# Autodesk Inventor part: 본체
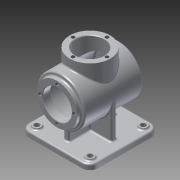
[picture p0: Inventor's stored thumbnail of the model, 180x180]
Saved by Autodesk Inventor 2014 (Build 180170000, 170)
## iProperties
Created: 2015-07
Part Number: 본체
Material: 알루미늄 6061
Document SubType Name: Modeling
Designer: L10
Density: 2.71 g/cm^3
Appearance: 알루미늄 - 평지
Author: L10
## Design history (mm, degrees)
sketch "스케치1"
  geometry: L1 (50, -65)-(-50, -65); L2 (-65, -50)-(-65, 50); L3 (-50, 65)-(50, 65); L4 (65, 50)-(65, -50); L5 (65, -65)-(-65, 65); L6 (-65, -65)-(65, 65); A1 r 15 centre (-50, 50) between (-50, 65) and (-65, 50); A2 r 15 centre (50, 50) between (65, 50) and (50, 65); A3 r 15 centre (50, -50) between (50, -65) and (65, -50); A4 r 15 centre (-50, -50) between (-65, -50) and (-50, -65); 1 further point
  constraints: 12 end point, 8 point on circle, 8 point on line, 8 tangent, 4 centre point, 3 equal radius, 2 midpoint, 2 parallel, 1 horizontal, 1 perpendicular
  dimensions: "d0" = 130 distance of L5.end L6.end; "d1" = 130 distance of L6.start L5.end; "d2" = 15 radius of A1
extrude "돌출1" new body sketch "스케치1" distance "d3" = 10; taper "d4" = 0 deg
fillet "모깎기1" dims "d5" = 3
sketch "스케치2"
  geometry: C1 r 7.5 at (-50, 50); C2 r 7.5 at (50, 50); C3 r 7.5 at (50, -50); C4 r 7.5 at (-50, -50); A1 r 12 centre (50, 50) between (62, 50) and (50, 62) reference; A2 r 12 centre (-50, 50) between (-50, 62) and (-62, 50) reference; A3 r 12 centre (-50, -50) between (-62, -50) and (-50, -62) reference; A4 r 12 centre (50, -50) between (50, -62) and (62, -50) reference; 1 further point
  constraints: 4 centre point, 4 coincident
  dimensions: "d6" = 15 diameter of C1; "d7" = 15 diameter of C2
extrude "돌출2" join sketch "스케치2" distance "d8" = 3; taper "d9" = 0 deg
fillet "모깎기2" dims "d10" = 3
hole "구멍1" diameter "d13" = 10; stored, may be unused: countersink angle "d17" = 90 deg, drill point angle "d19" = 118 deg; dims "d11" = 10, "d12" = 10, "d14" = 6, "d15" = 4, "d16" = 2, "d18" = 8
hole "구멍2" diameter "d22" = 10; stored, may be unused: countersink angle "d26" = 90 deg, drill point angle "d28" = 118 deg; dims "d20" = 10, "d21" = 10, "d23" = 6, "d24" = 4, "d25" = 2, "d27" = 8
hole "구멍3" diameter "d31" = 10; stored, may be unused: countersink angle "d35" = 90 deg, drill point angle "d37" = 118 deg; dims "d29" = 10, "d30" = 10, "d32" = 6, "d33" = 4, "d34" = 2, "d36" = 8
hole "구멍4" diameter "d40" = 10; stored, may be unused: countersink angle "d44" = 90 deg, drill point angle "d46" = 118 deg; dims "d38" = 10, "d39" = 10, "d41" = 6, "d42" = 4, "d43" = 2, "d45" = 8
sketch "스케치3"
  geometry: L1 (-45, -5)-(45, -5); L2 (45, -5)-(45, 5); L3 (45, 5)-(-45, 5); L4 (-45, 5)-(-45, -5); L5 (-45, -5)-(45, 5); L6 (45, -5)-(-45, 5); L7 (-5, -45)-(5, -45); L8 (5, -45)-(5, 45); L9 (5, 45)-(-5, 45); L10 (-5, 45)-(-5, -45); L11 (-5, -45)-(5, 45); L12 (5, -45)-(-5, 45); 1 further point
  constraints: 24 end point, 4 midpoint, 4 parallel, 2 horizontal, 2 perpendicular
  dimensions: "d47" = 90 distance of L3.end L2.end; "d48" = 10 distance of L2.end L1.end; "d49" = 10 distance of L9.end L8.end; "d50" = 90 distance of L8.end L7.end
extrude "돌출3" join sketch "스케치3" distance "d51" = 68; taper "d52" = 0 deg
fillet "모깎기3" dims "d53" = 3
sketch "스케치4"
  geometry: C1 r 38 at (0, 0); 1 further point
  constraints: 1 centre point, 1 coincident
  dimensions: "d54" = 76 diameter of C1
extrude "돌출4" join sketch "스케치4" distance "d55" = 62; taper "d56" = 0 deg
sketch "스케치5"
  geometry: L1 (0, 0)-(0, 78); C1 r 45 at (0, 78)
  constraints: 2 end point, 1 centre point, 1 coincident, 1 vertical
  dimensions: "d57" = 78 distance of L1.start L1.end; "d58" = 90 diameter of C1
extrude "돌출5" join sketch "스케치5" distance "d59" = 55; taper "d61" = 0 deg; dims "d60" = 48, "d62" = 0
sketch "스케치6"
  geometry: C1 r 45 at (0, 0) reference; C2 r 40 at (0, 0); 1 further point
  constraints: 1 centre point, 1 coincident
  dimensions: "d63" = 80 diameter of C2
extrude "돌출6" cut sketch "스케치6" distance "d64" = 96; taper "d65" = 0 deg
sketch "스케치7"
  geometry: C1 r 45 at (0, 0) reference; C2 r 45 at (0, 0); 1 further point
  constraints: 1 centre point, 1 coincident, 1 concentric
extrude "돌출7" join sketch "스케치7" distance "d66" = 7; taper "d67" = 0 deg
sketch "스케치8"
  geometry: C1 r 45 at (0, 0) reference; C2 r 38 at (0, 0); 1 further point
  constraints: 1 centre point, 1 coincident
  dimensions: "d68" = 76 diameter of C2
extrude "돌출8" join sketch "스케치8" distance "d69" = 7; taper "d70" = 0 deg
sketch "스케치9"
  geometry: C1 r 38 at (0, 0) reference; C2 r 27 at (0, 0); 1 further point
  constraints: 1 centre point, 1 coincident
  dimensions: "d71" = 54 diameter of C2
extrude "돌출9" cut sketch "스케치9" distance "d72" = 21; taper "d73" = 0 deg
fillet "모깎기4" dims "d74" = 3
sketch "스케치11"
  geometry: L1 (0, 0)-(0, 32); C1 r 38 at (0, 0) reference; 1 further point
  constraints: 2 end point, 1 vertical
  dimensions: "d75" = 32 distance of L1.start L1.end
hole "구멍5" sketch "스케치11" at (0, 32) diameter "d76" = 6.647; stored, may be unused: countersink angle "d80" = 90 deg, drill point angle "d82" = 118 deg; dims "d77" = 8, "d78" = 4, "d79" = 2, "d81" = 10
sketch "스케치12"
  geometry: C1 r 38 at (0, 0) reference; C2 r 27 at (0, 0)
  constraints: 1 centre point, 1 coincident
  dimensions: "d86" = 54 diameter of C2
extrude "돌출10" cut sketch "스케치12" stored distance "d87" = 30; taper "d88" = 0 deg
sketch "스케치13"
  geometry: L1 (0, 0)-(0, -32); C1 r 38 at (0, 0) reference
  constraints: 2 end point, 1 vertical
  dimensions: "d89" = 32 distance of L1.start L1.end
hole "구멍6" sketch "스케치13" at (0, -32) diameter "d90" = 6.647; stored, may be unused: countersink angle "d94" = 90 deg, drill point angle "d96" = 118 deg; dims "d91" = 8, "d92" = 4, "d93" = 2, "d95" = 10
sketch "스케치14"
  geometry: L1 (6.112, -4.172)-(-6.827, -4.172); L2 (-6.827, -4.172)-(-6.827, 2.918); L3 (-6.827, 2.918)-(6.112, 2.918); L4 (6.112, 2.918)-(6.112, -4.172); 1 further point
  constraints: 2 other
feature "엠보싱1" sketch "스케치14" dims "d0" = 130, "d1" = 130, "d2" = 15, "d100" = 0.5, "d101" = 0
chamfer "모따기1" distance "d102" = 1; stored, may be unused: second distance "d103" = 2, angle "d104" = 45 deg
node "솔리드1"
pattern_circular "원형 패턴1" dims angle "d84" = 360 deg
pattern_circular "원형 패턴2" dims angle "d98" = 360 deg
node "작업점1"
node "작업점2"
node "작업점3"
